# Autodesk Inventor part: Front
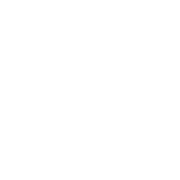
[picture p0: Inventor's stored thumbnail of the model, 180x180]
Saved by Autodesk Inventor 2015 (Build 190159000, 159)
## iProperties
Created: 2016-02
Part Number: Front
Material: Wood (Birch)
Document SubType Name: Modeling
Designer: Hafliði
Density: 0.55 g/cm^3
Appearance: Birch - Natural Polished
Mass: 770 g
Surface Area: 2980 cm^2
Volume: 1400 cm^3
Author: Hafliði
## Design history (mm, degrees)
sketch "Sketch1"
  geometry: L1 (-100, 350)-(100, 350); L2 (100, 350)-(100, -350); L3 (100, -350)-(-100, -350); L4 (-100, -350)-(-100, 350); L5 (-100, 350)-(100, -350); L6 (100, 350)-(-100, -350); 1 further point
  constraints: 12 end point, 2 midpoint, 2 parallel, 1 horizontal, 1 perpendicular
  dimensions: "d0" = 200 distance of L2.end L3.end; "d1" = 700 distance of L1.end L2.end
extrude "Extrusion1" new body sketch "Sketch1" distance "d2" = 10; taper "d3" = 0 deg
body "Solid1"
